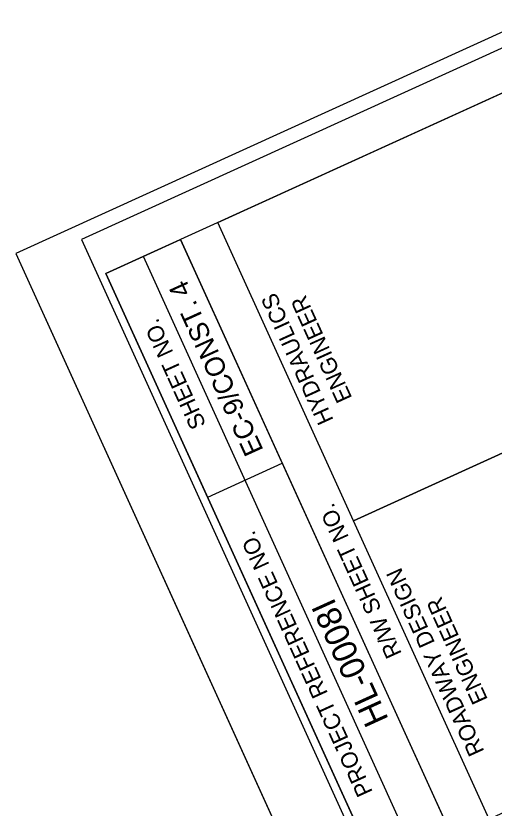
# Model space of a CAD drawing. Extents: x 2097233 to 2098987, y 683915 to 686009.
# Drawn here: x 2097292.8 to 2097438.9, y 685278 to 685519.9 of the extents above; entities that cross this region are included whole.
import ezdxf

# ---------------------------------------------------------------- set-up
doc = ezdxf.new("R2010")
doc.units = 0
for name, color, linetype in [('Sheet Cutting Line CELL', 7, 'Continuous'), ('Sheet Data Field CELL', 7, 'Continuous'), ('Sheet Plan CELL', 7, 'Continuous'), ('Sheet Plot Border Inside CELL', 7, 'Continuous'), ('Sheet Plot Border Outside CELL', 7, 'Continuous')]:
    doc.layers.add(name, color=color, linetype=linetype)

msp = doc.modelspace()

# ---------------------------------------------------------------- linework, layer by layer
at = {"layer": 'Sheet Cutting Line CELL'}
msp.add_line((2097292.78, 685447.36), (2097990.05, 683915.04), dxfattribs=at)
at = {"layer": 'Sheet Plan CELL'}
for p, q in [((2097425.97, 685269.5), (2097343.1, 685451.56)), ((2097425.97, 685269.5), (2097343.1, 685451.56)), ((2097414.56, 685264.29), (2097331.72, 685446.38)), ((2097395.9, 685365.73), (2097498.26, 685412.32)), ((2097351.43, 685372.92), (2097374.16, 685383.32))]:
    msp.add_line(p, q, dxfattribs=at)
for points in [[(2097320.28, 685441.22), (2097941.56, 684075.89), (2098897.27, 684510.77), (2098276, 685876.08)], [(2097395.9, 685365.73), (2097354.48, 685456.74), (2097456.88, 685503.35), (2097498.31, 685412.33)], [(2097403.14, 685259.11), (2097320.28, 685441.22), (2097343.1, 685451.56), (2097425.97, 685269.5)], [(2097437.34, 685274.67), (2097395.9, 685365.73), (2097498.31, 685412.33), (2097539.72, 685321.27)]]:
    msp.add_lwpolyline(points, close=True, dxfattribs=at)
at = {"layer": 'Sheet Plot Border Inside CELL'}
msp.add_lwpolyline([(2098963.13, 684372.11), (2098273.1, 685888.48), (2097312.85, 685451.54), (2098002.87, 683935.16)], close=True, dxfattribs=at)
at = {"layer": 'Sheet Plot Border Outside CELL'}
msp.add_lwpolyline([(2098986.71, 684368.56), (2098289.45, 685900.88), (2097292.78, 685447.36), (2097990.05, 683915.04)], close=True, dxfattribs=at)

# ---------------------------------------------------------------- texts
at = {"layer": 'Sheet Data Field CELL'}
for s, height, p in [('EC-9/CONST. 4', 6, (2097368.5, 685387.28)), ('HL-0008I', 7.5, (2097406.74, 685305.09))]:
    msp.add_text(s, height=height, rotation=114.4674, dxfattribs=at).set_placement(p)
at = {"layer": 'Sheet Plan CELL'}
for s, height, p in [('HYDRAULICS', 5, (2097389.9, 685396.47)), ('ENGINEER', 5, (2097395.59, 685403.2)), ('SHEET NO.', 5, (2097350.97, 685395.08)), ('R/W SHEET NO.', 5.0001, (2097410.73, 685325.18)), ('PROJECT REFERENCE NO.', 5.0001, (2097401.88, 685282.93)), ('ROADWAY DESIGN', 5.0001, (2097435.96, 685295.33)), ('ENGINEER', 5, (2097437.02, 685311.18))]:
    msp.add_text(s, height=height, rotation=114.4674, dxfattribs=at).set_placement(p)

doc.saveas('drawing.dxf')
